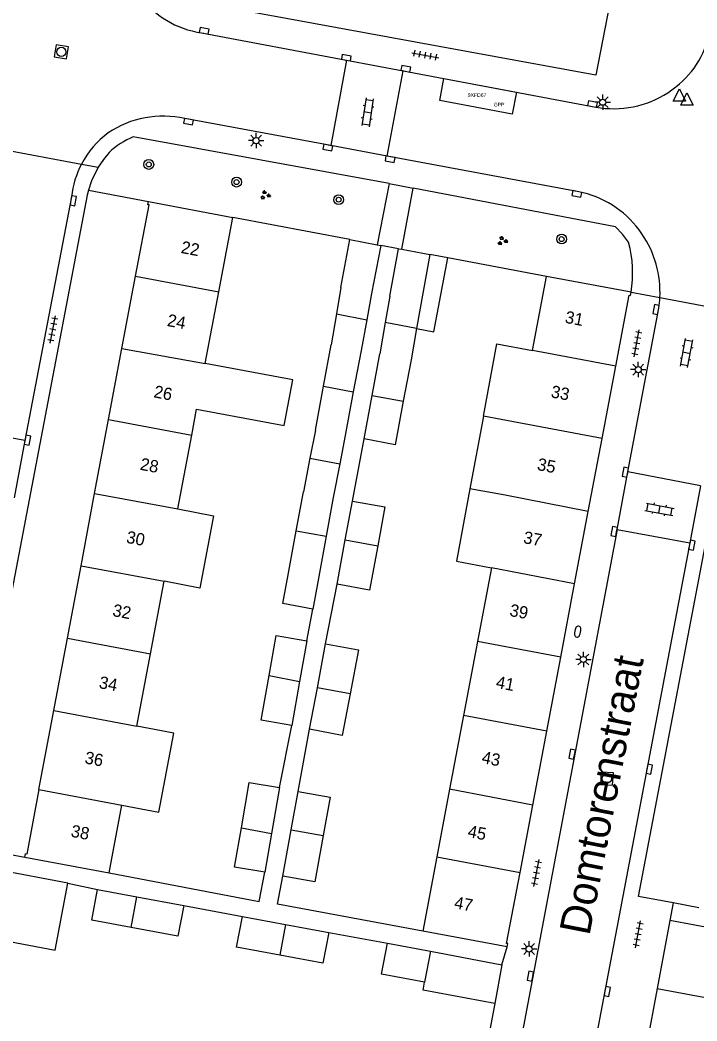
# Model space of a CAD drawing. Extents: x 131000 to 133014, y 396499 to 399001.
# Drawn here: x 131442.6 to 131497.7, y 397205.1 to 397286.7 of the extents above; entities that cross this region are included whole.
import ezdxf

# ---------------------------------------------------------------- set-up
doc = ezdxf.new("R2010")
doc.units = 0
for name, color, linetype in [('bp-anno-kenteken', 7, 'Continuous'), ('bp-grn-parkeervak', 7, 'Continuous'), ('gg-afsc-erfafscheiding', 7, 'Continuous'), ('gg-afsc-muur', 7, 'Continuous'), ('gg-anno-huisnummerreeks BGT', 7, 'Continuous'), ('gg-anno-openbare ruimte label', 7, 'Continuous'), ('gg-bbg-bijgebouw', 7, 'Continuous'), ('gg-bbg-gedigitaliseerde bebouwing', 7, 'Continuous'), ('gg-bbg-gedigitaliseerde bijgebouw', 7, 'Continuous'), ('gg-bbg-hoofdgebouw', 7, 'Continuous'), ('gg-bbg-luifel en loopbrug', 7, 'Continuous'), ('gg-bbg-tussenscheiding', 7, 'Continuous'), ('gg-knt-verharding', 7, 'Continuous'), ('gt-grn-vlakafsluiter', 7, 'Continuous'), ('gt-grn-weggrens', 7, 'Continuous'), ('gt-symb-boom', 7, 'Continuous'), ('gt-symb-brandkraan', 7, 'Continuous'), ('gt-symb-groenvak', 7, 'Continuous'), ('gt-symb-klinker verharding', 7, 'Continuous'), ('gt-symb-kolk', 7, 'Continuous'), ('gt-symb-lichtmast', 7, 'Continuous'), ('gt-symb-rioolschacht', 7, 'Continuous'), ('gt-symb-tegel verharding', 7, 'Continuous'), ('gt-symb-waterafsluiter', 7, 'Continuous'), ('kenmerkpunt gehandicapten parkeerplaats', 7, 'Continuous')]:
    doc.layers.add(name, color=color, linetype=linetype)

# ---------------------------------------------------------------- blocks, each defined once
blk = doc.blocks.new('gt0-RS')
at = {"layer": 'gt-symb-rioolschacht'}
blk.add_lwpolyline([(-0.5, -0.5), (0.5, -0.5), (0.5, 0.5), (-0.5, 0.5)], close=True, dxfattribs=at)
blk.add_circle((0, 0), 0.375, dxfattribs=at)
blk = doc.blocks.new('gt0-KOLK')
at = {"layer": 'gt-symb-kolk'}
blk.add_lwpolyline([(0, 0), (0.375, 0), (0.375, 0.4), (-0.375, 0.4), (-0.375, 0), (0, 0)], dxfattribs=at)
blk = doc.blocks.new('gt0-TEG1')
at = {"layer": 'gt-symb-tegel verharding'}
for p, q in [((-1.125, 0), (1.125, 0)), ((-0.9, -0.25), (-0.9, 0.25)), ((-0.45, -0.25), (-0.45, 0.25)), ((0, -0.25), (0, 0.25)), ((0.45, -0.25), (0.45, 0.25)), ((0.9, -0.25), (0.9, 0.25))]:
    blk.add_line(p, q, dxfattribs=at)
blk = doc.blocks.new('gt0-LMAST')
at = {"layer": 'gt-symb-lichtmast'}
for p, q in [((-0.182, 0.173), (-0.447, 0.438)), ((-0.005, 0.246), (-0.005, 0.621)), ((0.172, 0.173), (0.437, 0.438)), ((-0.255, -0.004), (-0.63, -0.004)), ((-0.182, -0.181), (-0.447, -0.446)), ((-0.005, -0.254), (-0.005, -0.629)), ((0.437, -0.446), (0.172, -0.181)), ((0.245, -0.004), (0.62, -0.004))]:
    blk.add_line(p, q, dxfattribs=at)
blk.add_circle((-0.005, -0.004), 0.25, dxfattribs=at)
blk = doc.blocks.new('gt0-KL1')
at = {"layer": 'gt-symb-klinker verharding'}
for p, q in [((-1.15, 0.3), (1.15, 0.3)), ((-1, -0.3), (-1, 0.3)), ((-0.5, 0.3), (-0.5, 0.45)), ((0, -0.3), (0, 0.3)), ((0.5, 0.3), (0.5, 0.45)), ((1, -0.3), (1, 0.3)), ((-1.15, -0.3), (1.15, -0.3)), ((-0.5, -0.45), (-0.5, -0.3)), ((0.5, -0.45), (0.5, -0.3))]:
    blk.add_line(p, q, dxfattribs=at)
blk = doc.blocks.new('gt0-BR')
at = {"layer": 'gt-symb-brandkraan'}
for centre, radius, start, end in [((-0.244, 0), 0.206, 107.56694, 252.43307), ((0.599, -2.664), 3, 106.89205, 107.56694), ((0, -0.691), 0.938, 73.10799, 106.89205), ((-0.599, -2.664), 3, 72.43309, 73.10799), ((0.244, 0), 0.206, 287.56695, 72.43309), ((0.599, 2.664), 3, 252.43307, 253.10797), ((0, 0.691), 0.938, 253.10797, 286.89206), ((-0.599, 2.664), 3, 286.89206, 287.56695)]:
    blk.add_arc(centre, radius, start, end, dxfattribs=at)
blk = doc.blocks.new('gt0-GRVAK')
at = {"layer": 'gt-symb-groenvak'}
for p, q in [((-0.11, 0.189), (-0.228, 0.24)), ((-0.182, 0.153), (0.088, 0.153)), ((-0.091, 0.211), (-0.156, 0.322)), ((-0.047, 0.214), (-0.047, 0.393)), ((-0.004, 0.211), (0.061, 0.322)), ((0.015, 0.189), (0.133, 0.24)), ((0.262, -0.052), (0.197, 0.059)), ((0.305, -0.049), (0.305, 0.13)), ((0.349, -0.052), (0.414, 0.059)), ((-0.245, -0.228), (-0.363, -0.177)), ((-0.318, -0.264), (-0.047, -0.264)), ((-0.226, -0.206), (-0.291, -0.095)), ((-0.183, -0.203), (-0.183, -0.024)), ((-0.139, -0.206), (-0.074, -0.095)), ((-0.12, -0.228), (-0.002, -0.177)), ((0.243, -0.074), (0.125, -0.023)), ((0.17, -0.11), (0.441, -0.11)), ((0.368, -0.074), (0.486, -0.023))]:
    blk.add_line(p, q, dxfattribs=at)
blk = doc.blocks.new('gt0-BOOM')
at = {"layer": 'gt-symb-boom'}
for radius in [0.4, 0.2]:
    blk.add_circle((0, 0), radius, dxfattribs=at)
blk = doc.blocks.new('gt0-WAFSL')
at = {"layer": 'gt-symb-waterafsluiter'}
for p, q in [((-0.5, -0.333), (0, 0.667)), ((0, 0.667), (0.5, -0.333)), ((0.5, -0.333), (-0.5, -0.333))]:
    blk.add_line(p, q, dxfattribs=at)

msp = doc.modelspace()

# ---------------------------------------------------------------- linework, layer by layer
at = {"layer": 'bp-grn-parkeervak'}
msp.add_lwpolyline([(131483.009, 397280.79), (131482.672, 397279.001), (131476.77, 397280.114), (131477.107, 397281.903), (131483.009, 397280.79)], dxfattribs=at)
at = {"layer": 'gg-afsc-erfafscheiding'}
for p, q in [((131469.644, 397247.466), (131470.6, 397252.524)), ((131467.467, 397235.836), (131468.403, 397240.696)), ((131465.939, 397236.059), (131466.425, 397238.658)), ((131463.698, 397224.111), (131464.702, 397229.159)), ((131465.238, 397223.795), (131466.157, 397228.862)), ((131446.47, 397216.31), (131448.89, 397215.808)), ((131495.77, 397214.71), (131492.951, 397215.241)), ((131455.911, 397214.5), (131460.689, 397213.61)), ((131497.87, 397214.314), (131495.77, 397214.71)), ((131467.717, 397212.302), (131472.498, 397211.435))]:
    msp.add_line(p, q, dxfattribs=at)
for points in [[(131449.82, 397217.147), (131462.06, 397214.836), (131462.507, 397217.202)], [(131475.38, 397212.41), (131463.556, 397214.613), (131463.979, 397216.886)]]:
    msp.add_lwpolyline(points, dxfattribs=at)
at = {"layer": 'gg-afsc-muur'}
for p, q in [((131469.433, 397268.776), (131459.9, 397270.57)), ((131485.46, 397265.77), (131477.43, 397267.273)), ((131494.491, 397207.721), (131493.464, 397202.35)), ((131481.241, 397206.522), (131479.716, 397198.455))]:
    msp.add_line(p, q, dxfattribs=at)
at = {"layer": 'gg-bbg-bijgebouw'}
for p, q in [((131469.433, 397268.776), (131471.673, 397268.355)), ((131471.673, 397268.355), (131471.958, 397268.301)), ((131473.413, 397268.028), (131473.667, 397267.98)), ((131473.667, 397267.98), (131475.968, 397267.547)), ((131446.47, 397216.31), (131440.57, 397217.43)), ((131495.524, 397213.268), (131494.491, 397207.721)), ((131501.331, 397212.174), (131495.524, 397213.268)), ((131472.498, 397211.435), (131476.006, 397210.771)), ((131476.006, 397210.771), (131481.822, 397209.669)), ((131481.822, 397209.669), (131481.241, 397206.522)), ((131494.491, 397207.721), (131500.282, 397206.644))]:
    msp.add_line(p, q, dxfattribs=at)
msp.add_lwpolyline([(131439.54, 397211.98), (131445.44, 397210.86), (131446.47, 397216.31)], dxfattribs=at)
at = {"layer": 'gg-bbg-gedigitaliseerde bebouwing'}
for p, q in [((131458.76, 397264.527), (131459.9, 397270.57)), ((131484.318, 397259.727), (131485.46, 397265.77)), ((131457.654, 397258.666), (131458.76, 397264.527)), ((131456.552, 397252.827), (131456.953, 397254.952)), ((131480.328, 397254.369), (131479.229, 397248.47)), ((131455.419, 397246.82), (131456.552, 397252.827)), ((131480.974, 397242.023), (131479.841, 397236.025)), ((131453.19, 397235.007), (131454.306, 397240.923)), ((131479.841, 397236.025), (131478.702, 397229.996)), ((131452.079, 397229.121), (131453.19, 397235.007)), ((131478.702, 397229.996), (131477.563, 397223.968)), ((131477.563, 397223.968), (131476.523, 397218.463)), ((131449.82, 397217.147), (131450.862, 397222.669)), ((131476.523, 397218.463), (131475.38, 397212.41))]:
    msp.add_line(p, q, dxfattribs=at)
for points in [[(131480.328, 397254.369), (131481.426, 397260.266), (131484.318, 397259.727)], [(131456.953, 397254.952), (131464.088, 397253.615), (131464.784, 397257.33), (131457.654, 397258.666)], [(131479.229, 397248.47), (131478.127, 397242.553), (131480.974, 397242.023)], [(131455.419, 397246.82), (131458.329, 397246.271), (131457.217, 397240.374), (131454.306, 397240.923)], [(131450.862, 397222.669), (131453.883, 397222.1), (131455.1, 397228.552), (131452.079, 397229.121)]]:
    msp.add_lwpolyline(points, dxfattribs=at)
at = {"layer": 'gg-bbg-gedigitaliseerde bijgebouw'}
for p, q in [((131468.696, 397264.862), (131469.433, 397268.776)), ((131471.958, 397268.301), (131471.216, 397264.385)), ((131472.686, 397264.165), (131473.413, 397268.028)), ((131475.968, 397267.547), (131474.864, 397261.517)), ((131468.696, 397264.862), (131468.342, 397262.709)), ((131471.216, 397264.385), (131470.817, 397262.24)), ((131472.686, 397264.165), (131472.321, 397262.002)), ((131468.342, 397262.709), (131467.926, 397260.183)), ((131470.817, 397262.24), (131470.35, 397259.732)), ((131472.321, 397262.002), (131471.89, 397259.452)), ((131474.864, 397261.517), (131474.423, 397258.98)), ((131467.302, 397256.829), (131467.926, 397260.183)), ((131470.35, 397259.732), (131469.723, 397256.361)), ((131471.26, 397256.069), (131471.89, 397259.452)), ((131474.423, 397258.98), (131473.792, 397255.594)), ((131466.635, 397253.244), (131467.302, 397256.829)), ((131469.723, 397256.361), (131469.059, 397252.793)), ((131470.6, 397252.524), (131471.26, 397256.069)), ((131466.635, 397253.244), (131466.19, 397250.964)), ((131469.059, 397252.793), (131468.616, 397250.495)), ((131466.19, 397250.964), (131465.651, 397248.204)), ((131468.616, 397250.495), (131468.089, 397247.761)), ((131465.076, 397245.037), (131465.651, 397248.204)), ((131468.089, 397247.761), (131467.513, 397244.587)), ((131469.063, 397244.298), (131469.644, 397247.466)), ((131464.426, 397241.455), (131465.076, 397245.037)), ((131467.513, 397244.587), (131466.864, 397241.013)), ((131468.403, 397240.696), (131469.063, 397244.298)), ((131466.864, 397241.013), (131466.425, 397238.658)), ((131465.939, 397236.059), (131465.348, 397232.763)), ((131466.794, 397232.251), (131467.467, 397235.836)), ((131465.348, 397232.763), (131464.702, 397229.159)), ((131466.157, 397228.862), (131466.794, 397232.251)), ((131463.698, 397224.111), (131463.054, 397220.377)), ((131464.669, 397220.675), (131465.238, 397223.795)), ((131463.054, 397220.377), (131462.507, 397217.202)), ((131463.979, 397216.886), (131464.669, 397220.675)), ((131448.89, 397215.808), (131452.084, 397215.213)), ((131452.084, 397215.213), (131455.911, 397214.5)), ((131460.689, 397213.61), (131464.198, 397212.957)), ((131464.198, 397212.957), (131467.717, 397212.302))]:
    msp.add_line(p, q, dxfattribs=at)
for points in [[(131473.792, 397255.594), (131473.133, 397252.053), (131470.6, 397252.524)], [(131469.644, 397247.466), (131472.29, 397246.981), (131471.707, 397243.802)], [(131471.707, 397243.802), (131471.049, 397240.211), (131468.403, 397240.696)], [(131466.425, 397238.658), (131463.99, 397239.112), (131464.426, 397241.455)], [(131462.863, 397233.233), (131463.45, 397236.505), (131465.939, 397236.059)], [(131467.467, 397235.836), (131470.135, 397235.335), (131469.461, 397231.746)], [(131464.702, 397229.159), (131462.213, 397229.605), (131462.863, 397233.233)], [(131469.461, 397231.746), (131468.825, 397228.361), (131466.157, 397228.862)], [(131460.606, 397220.837), (131461.244, 397224.534), (131463.698, 397224.111)], [(131465.238, 397223.795), (131467.836, 397223.321), (131467.265, 397220.189)], [(131462.507, 397217.202), (131460.052, 397217.626), (131460.606, 397220.837)], [(131467.265, 397220.189), (131466.577, 397216.413), (131463.979, 397216.886)], [(131451.616, 397212.697), (131448.417, 397213.293), (131448.89, 397215.808)], [(131455.911, 397214.5), (131455.437, 397211.984), (131451.616, 397212.697)], [(131463.744, 397210.439), (131460.215, 397211.096), (131460.689, 397213.61)], [(131467.717, 397212.302), (131467.244, 397209.787), (131463.744, 397210.439)], [(131475.531, 397208.244), (131472.022, 397208.904), (131472.498, 397211.435)], [(131481.241, 397206.522), (131475.412, 397207.598), (131475.531, 397208.244)]]:
    msp.add_lwpolyline(points, dxfattribs=at)
at = {"layer": 'gg-bbg-hoofdgebouw'}
for p, q in [((131452.98, 397271.615), (131453.03, 397271.88)), ((131453.03, 397271.88), (131459.9, 397270.57)), ((131450.873, 397259.892), (131451.985, 397265.798)), ((131492.36, 397264.48), (131485.46, 397265.77)), ((131492.313, 397264.229), (131492.36, 397264.48)), ((131449.781, 397254.1), (131450.873, 397259.892)), ((131489.994, 397252.562), (131491.109, 397258.457)), ((131448.647, 397248.08), (131449.781, 397254.1)), ((131488.87, 397246.618), (131489.994, 397252.562)), ((131447.537, 397242.193), (131448.647, 397248.08)), ((131487.755, 397240.722), (131488.87, 397246.618)), ((131446.425, 397236.287), (131447.537, 397242.193)), ((131486.624, 397234.739), (131487.755, 397240.722)), ((131445.312, 397230.382), (131446.425, 397236.287)), ((131485.484, 397228.712), (131486.624, 397234.739)), ((131444.098, 397223.941), (131445.312, 397230.382)), ((131484.345, 397222.684), (131485.484, 397228.712)), ((131483.304, 397217.179), (131484.345, 397222.684)), ((131442.96, 397218.44), (131443.01, 397218.705)), ((131442.96, 397218.44), (131449.82, 397217.147)), ((131482.27, 397211.12), (131475.38, 397212.41)), ((131482.27, 397211.12), (131482.321, 397211.39))]:
    msp.add_line(p, q, dxfattribs=at)
for points in [[(131451.985, 397265.798), (131453.078, 397271.596), (131452.98, 397271.615)], [(131491.109, 397258.457), (131492.204, 397264.249), (131492.313, 397264.229)], [(131444.098, 397223.941), (131443.108, 397218.687), (131443.01, 397218.705)], [(131482.321, 397211.39), (131482.213, 397211.41), (131483.304, 397217.179)]]:
    msp.add_lwpolyline(points, dxfattribs=at)
at = {"layer": 'gg-bbg-luifel en loopbrug'}
msp.add_line((131477.43, 397267.273), (131475.968, 397267.547), dxfattribs=at)
msp.add_lwpolyline([(131474.864, 397261.517), (131476.294, 397261.247), (131477.43, 397267.273)], dxfattribs=at)
at = {"layer": 'gg-bbg-tussenscheiding'}
for p, q in [((131451.985, 397265.798), (131458.76, 397264.527)), ((131468.342, 397262.709), (131470.817, 397262.24)), ((131474.864, 397261.517), (131472.321, 397262.002)), ((131450.873, 397259.892), (131457.654, 397258.666)), ((131491.109, 397258.457), (131484.318, 397259.727)), ((131467.302, 397256.829), (131469.723, 397256.361)), ((131471.26, 397256.069), (131473.792, 397255.594)), ((131483.205, 397253.831), (131480.328, 397254.369)), ((131449.781, 397254.1), (131456.552, 397252.827)), ((131489.994, 397252.562), (131483.205, 397253.831)), ((131466.19, 397250.964), (131468.616, 397250.495)), ((131448.647, 397248.08), (131455.419, 397246.82)), ((131482.091, 397247.935), (131479.229, 397248.47)), ((131488.87, 397246.618), (131482.091, 397247.935)), ((131465.076, 397245.037), (131467.513, 397244.587)), ((131469.063, 397244.298), (131471.707, 397243.802)), ((131447.537, 397242.193), (131454.306, 397240.923)), ((131487.755, 397240.722), (131480.974, 397242.023)), ((131446.425, 397236.287), (131453.19, 397235.007)), ((131486.624, 397234.739), (131479.841, 397236.025)), ((131462.863, 397233.233), (131465.348, 397232.763)), ((131469.461, 397231.746), (131466.794, 397232.251)), ((131445.312, 397230.382), (131452.079, 397229.121)), ((131485.484, 397228.712), (131478.702, 397229.996)), ((131444.098, 397223.941), (131450.862, 397222.669)), ((131484.345, 397222.684), (131477.563, 397223.968)), ((131460.606, 397220.837), (131463.054, 397220.377)), ((131464.669, 397220.675), (131467.265, 397220.189)), ((131476.523, 397218.463), (131483.304, 397217.179)), ((131451.616, 397212.697), (131452.084, 397215.213)), ((131464.198, 397212.957), (131463.744, 397210.439)), ((131476.006, 397210.771), (131475.531, 397208.244))]:
    msp.add_line(p, q, dxfattribs=at)
at = {"layer": 'gg-knt-verharding'}
for p, q in [((131457.34, 397285.63), (131469.156, 397283.402)), ((131469.156, 397283.402), (131467.878, 397276.43)), ((131469.156, 397283.402), (131473.783, 397282.53)), ((131472.478, 397275.575), (131473.783, 397282.53)), ((131473.783, 397282.53), (131489.48, 397279.57)), ((131495.344, 397280.748), (131496.01, 397281.23)), ((131467.878, 397276.43), (131456, 397278.64)), ((131472.633, 397273.337), (131451.798, 397277.138)), ((131472.478, 397275.575), (131467.878, 397276.43)), ((131488.09, 397272.67), (131472.478, 397275.575)), ((131472.633, 397273.337), (131471.673, 397268.355)), ((131446.76, 397272.26), (131442.969, 397252.389)), ((131473.667, 397267.98), (131474.605, 397272.969)), ((131491.081, 397269.815), (131474.605, 397272.969)), ((131493.234, 397269.246), (131493, 397269.57)), ((131493.243, 397269.234), (131493.234, 397269.246)), ((131492.095, 397249.836), (131494.61, 397263.18)), ((131442.969, 397252.389), (131436.994, 397253.52)), ((131442.969, 397252.389), (131442.078, 397247.714)), ((131491.208, 397245.13), (131492.095, 397249.836)), ((131498.022, 397248.715), (131492.095, 397249.836)), ((131498.022, 397248.715), (131497.14, 397244.055)), ((131491.208, 397245.13), (131480.88, 397190.311)), ((131491.208, 397245.13), (131497.14, 397244.055)), ((131497.14, 397244.055), (131486.741, 397189.111)), ((131440.89, 397218.81), (131442.96, 397218.44))]:
    msp.add_line(p, q, dxfattribs=at)
for points in [[(131490.78, 397288.92), (131489.47, 397282.17), (131453.72, 397288.74)], [(131449.82, 397275.88), (131449.355, 397275.299), (131448.946, 397274.677)], [(131448.946, 397274.677), (131448.401, 397273.574), (131448.159, 397272.809)], [(131448.159, 397272.809), (131448.03, 397272.4), (131437.94, 397219.43), (131440.89, 397218.81)], [(131492.15, 397268.55), (131491.655, 397269.216), (131491.081, 397269.815)], [(131492.951, 397215.241), (131501.8, 397261.76), (131502.003, 397262.448)]]:
    msp.add_lwpolyline(points, dxfattribs=at)
for centre, radius, start, end in [((131458.375, 397292.974), 7.417, 214.99983, 261.97564), ((131491.309, 397287.231), 7.623, 308.07805, 350.63381), ((131490.93, 397287.537), 8.098, 259.68553, 303.03203), ((131454.229, 397270.784), 8.053, 77.29572, 123.87727), ((131454.269, 397271.425), 7.553, 126.83919, 152.33482), ((131454.196, 397271.184), 6.419, 111.93552, 132.97687), ((131454.278, 397271.417), 7.565, 152.31502, 173.60312), ((131486.528, 397264.758), 8.065, 36.63373, 78.83254), ((131486.342, 397264.495), 8.371, 356.89511, 34.47615), ((131482.732, 397266.024), 9.751, 350.89196, 15.01538), ((131486.495, 397264.473), 8.218, 350.95053, 356.99686)]:
    msp.add_arc(centre, radius, start, end, dxfattribs=at)
at = {"layer": 'gt-grn-vlakafsluiter'}
msp.add_line((131448.159, 397272.809), (131453.03, 397271.88), dxfattribs=at)
at = {"layer": 'gt-grn-weggrens'}
for p, q in [((131440.896, 397276.176), (131447.579, 397274.932)), ((131447.579, 397274.932), (131448.946, 397274.677)), ((131472.633, 397273.337), (131474.605, 397272.969)), ((131473.413, 397268.028), (131471.958, 397268.301)), ((131492.36, 397264.48), (131494.701, 397264.042)), ((131494.701, 397264.042), (131500.801, 397262.901)), ((131495.77, 397214.71), (131495.524, 397213.268)), ((131481.822, 397209.669), (131482.27, 397211.12))]:
    msp.add_line(p, q, dxfattribs=at)

# ---------------------------------------------------------------- block references
at = {"layer": 'gt-symb-boom'}
for p in [(131453.057, 397274.899), (131460.211, 397273.458), (131468.526, 397272.025), (131486.695, 397268.815)]:
    msp.add_blockref('gt0-BOOM', p, dxfattribs=at)
at = {"layer": 'gt-symb-brandkraan', "rotation": -100.25359802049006}
msp.add_blockref('gt0-BR', (131488.001, 397236.823), dxfattribs=at)
at = {"layer": 'gt-symb-groenvak'}
for p in [(131462.545, 397272.4), (131481.861, 397268.667)]:
    msp.add_blockref('gt0-GRVAK', p, dxfattribs=at)
at = {"layer": 'gt-symb-klinker verharding'}
for p, rotation in [((131470.884, 397279.157), -98.62422873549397), ((131496.877, 397259.529), 79.28535610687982), ((131494.671, 397246.784), -10.837910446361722)]:
    msp.add_blockref('gt0-KL1', p, dxfattribs=dict(at, rotation=rotation))
at = {"layer": 'gt-symb-kolk'}
for p, rotation in [((131457.537, 397285.593), -10.366322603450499), ((131469.117, 397283.409), -10.422654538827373), ((131473.962, 397282.497), -11.478482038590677), ((131489.176, 397279.627), -10.25359802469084), ((131456.329, 397278.578), 169.69002960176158), ((131467.68, 397276.467), 168.86988891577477), ((131472.752, 397275.523), 169.51061018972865), ((131446.706, 397271.974), -99.9615165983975), ((131487.972, 397272.692), 168.57767893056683), ((131494.582, 397263.039), 79.39794170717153), ((131442.983, 397252.47), -100.83791044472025), ((131492.082, 397249.774), 79.28535610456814), ((131491.17, 397244.95), 79.28535610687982), ((131497.113, 397243.911), -100.83791044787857), ((131487.746, 397226.787), 79.2183832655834), ((131493.649, 397225.644), -100.65836150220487), ((131484.343, 397208.708), 78.7574742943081), ((131490.225, 397207.53), -100.71464389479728)]:
    msp.add_blockref('gt0-KOLK', p, dxfattribs=dict(at, rotation=rotation))
at = {"layer": 'gt-symb-lichtmast'}
for p in [(131490.048, 397279.975), (131461.81, 397276.844), (131492.939, 397258.18), (131488.474, 397234.552), (131484.052, 397210.959)]:
    msp.add_blockref('gt0-LMAST', p, dxfattribs=at)
at = {"layer": 'gt-symb-rioolschacht'}
for p, rotation in [((131445.932, 397284.071), -9.500010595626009), ((131490.384, 397224.837), -93.72642588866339)]:
    msp.add_blockref('gt0-RS', p, dxfattribs=dict(at, rotation=rotation))
at = {"layer": 'gt-symb-tegel verharding'}
for p, rotation in [((131475.587, 397283.798), -10.658361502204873), ((131445.246, 397261.448), 79.21838326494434), ((131492.815, 397260.319), 79.34163849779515), ((131484.645, 397217.149), 79.28535610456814), ((131492.927, 397212.15), 79.39794170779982)]:
    msp.add_blockref('gt0-TEG1', p, dxfattribs=dict(at, rotation=rotation))
at = {"layer": 'gt-symb-waterafsluiter'}
for p in [(131496.294, 397280.387), (131496.906, 397280.074)]:
    msp.add_blockref('gt0-WAFSL', p, dxfattribs=at)

# ---------------------------------------------------------------- texts
at = {"layer": 'bp-anno-kenteken'}
msp.add_text('9XFD67', height=0.3, dxfattribs=at).set_placement((131479.047, 397280.406))
at = {"layer": 'gg-anno-huisnummerreeks BGT'}
for s, p in [('22', (131455.623, 397267.692)), ('24', (131454.501, 397261.739)), ('31', (131486.917, 397261.998)), ('26', (131453.406, 397255.925)), ('33', (131485.769, 397255.925)), ('28', (131452.293, 397250.02)), ('35', (131484.649, 397250.005)), ('30', (131451.171, 397244.066)), ('37', (131483.522, 397244.045)), ('32', (131450.048, 397238.103)), ('39', (131482.4, 397238.109)), ('34', (131448.941, 397232.228)), ('41', (131481.291, 397232.245)), ('36', (131447.784, 397226.091)), ('43', (131480.132, 397226.113)), ('38', (131446.657, 397220.111)), ('45', (131478.992, 397220.084)), ('47', (131477.893, 397214.273))]:
    msp.add_text(s, height=1, rotation=349.3, dxfattribs=at).set_placement(p)
at = {"layer": 'gg-anno-openbare ruimte label'}
msp.add_text('Domtorenstraat', height=2.5, rotation=78.9, dxfattribs=at).set_placement((131488.953, 397211.972))
at = {"layer": 'kenmerkpunt gehandicapten parkeerplaats'}
msp.add_text('GPP', height=0.3, dxfattribs=at).set_placement((131481.162, 397279.624))

doc.saveas('drawing.dxf')
